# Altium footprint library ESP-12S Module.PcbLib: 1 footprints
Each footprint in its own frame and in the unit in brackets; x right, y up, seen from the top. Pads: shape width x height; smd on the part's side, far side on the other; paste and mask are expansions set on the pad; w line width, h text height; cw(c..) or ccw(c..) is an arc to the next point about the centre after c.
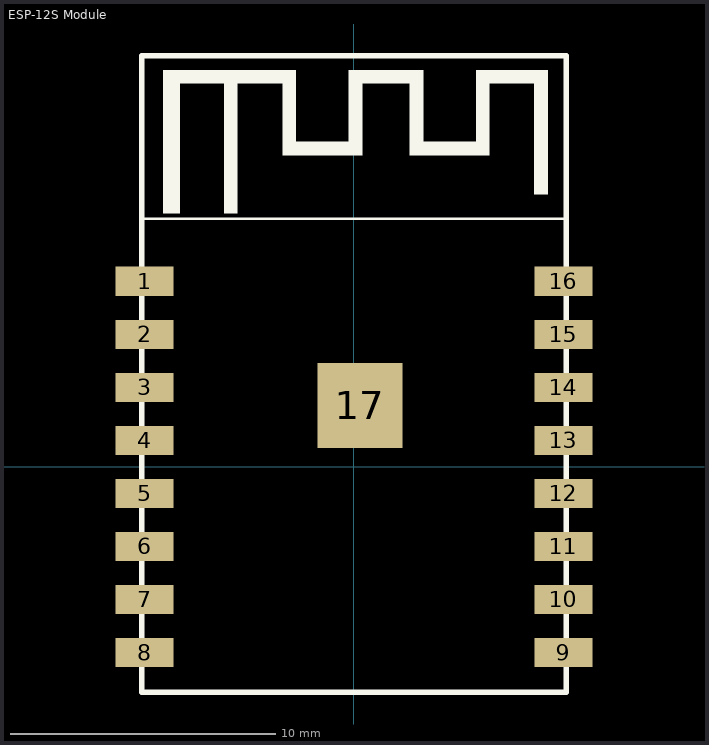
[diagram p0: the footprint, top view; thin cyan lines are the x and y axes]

## ESP-12S Module [mm]
pads (17):
  rect 2.2x1.1 smd: 1(-7.9,7) 2(-7.9,5) 3(-7.9,3) 4(-7.9,1) 5(-7.9,-1) 6(-7.9,-3) 7(-7.9,-5) 8(-7.9,-7) 9(7.9,-7) 10(7.9,-5) 11(7.9,-3) 12(7.9,-1) 13(7.9,1) 14(7.9,3) 15(7.9,5) 16(7.9,7)
  rect 3.2x3.2 smd: 17(0.22,2.321)
Top Overlay:
  region: -7.196,14.716 -7.196,9.563 -6.569,9.563 -6.569,14.716
  region: -7.196,14.463 -7.196,14.963 -2.196,14.963 -2.196,12.263 -0.196,12.263 -0.196,14.963 2.604,14.963 2.604,12.263 4.604,12.263 4.604,14.963 7.304,14.963 7.304,10.29 6.804,10.29 6.804,14.463 5.104,14.463 5.104,11.763 2.104,11.763 2.104,14.463 0.304,14.463 0.304,11.763 -2.696,11.763 -2.696,14.463 -4.396,14.463 -4.396,9.563 -4.896,9.563 -4.896,14.463
  lines w0.1: -8,9.354 8,9.354
  lines w0.2: -8,-8.496 -8,15.504 8,15.504 8,-8.496 -8,-8.496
